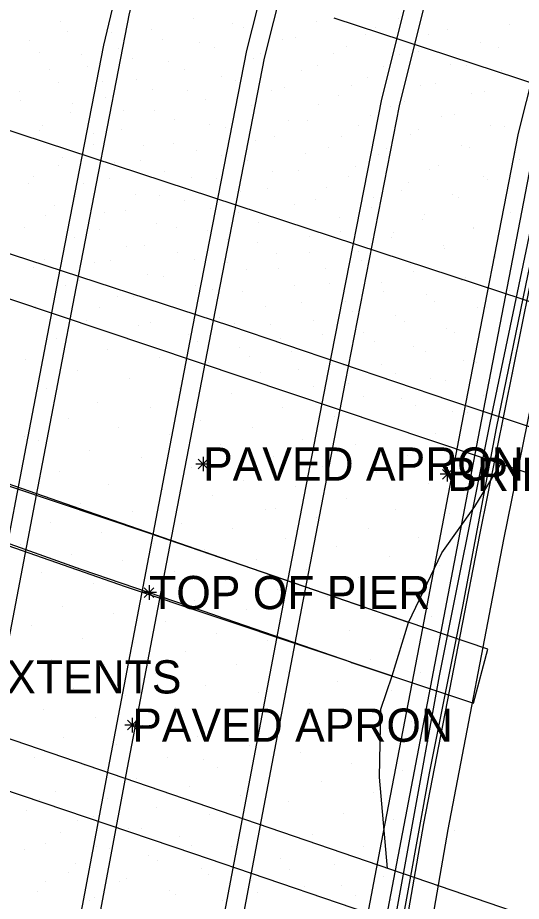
# Model space of a CAD drawing. Extents: x 1733582 to 1734070, y 467256 to 468256.
# Drawn here: x 1733841.15 to 1733868.45, y 467736.94 to 467784.83 of the extents above; entities that cross this region are included whole.
import ezdxf

# ---------------------------------------------------------------- set-up
doc = ezdxf.new("R2010")
doc.units = 0
for name, color, linetype in [('Default', 7, 'Continuous'), ('S_Bridge_Column_Square', 7, 'Continuous'), ('S_Bridge_Curb', 7, 'Continuous'), ('S_Bridge_Deck', 7, 'Continuous'), ('S_Bridge_Rail', 7, 'Continuous'), ('S_Ground_LevelString', 7, 'Continuous'), ('S_Ground_SpotElevation', 7, 'Continuous'), ('S_Guardrail_Beam', 7, 'Continuous'), ('S_Misc_MiscFeature', 7, 'Continuous'), ('S_Misc_MiscItems', 7, 'Continuous'), ('S_Roadway_Edge_Pavement', 7, 'Continuous'), ('S_Roadway_Painted_Lines', 7, 'Continuous'), ('S_Text', 7, 'Continuous')]:
    doc.layers.add(name, color=color, linetype=linetype)

# ---------------------------------------------------------------- blocks, each defined once
blk = doc.blocks.new('POINT_DISPLAY')
at = {"layer": 'Default'}
blk.add_line((0, 0), (0, 0), dxfattribs=at)

msp = doc.modelspace()

# ---------------------------------------------------------------- linework, layer by layer
at = {"layer": 'S_Bridge_Column_Square'}
msp.add_lwpolyline([(1733835.014, 467758.174), (1733846.976, 467754), (1733861.457, 467749.164), (1733862.347, 467752.05), (1733848.201, 467756.91), (1733835.866, 467761.044), (1733835.014, 467758.174)], dxfattribs=at)
at = {"layer": 'S_Bridge_Curb'}
msp.add_lwpolyline([(1733850.525, 467652.736), (1733851.676, 467663.636), (1733852.883, 467674.082), (1733854.262, 467685.548), (1733855.565, 467694.75), (1733856.845, 467703.748), (1733858.974, 467717.399), (1733861.233, 467731.524), (1733863.482, 467743.881), (1733865.283, 467752.922), (1733867.113, 467762.582), (1733868.83, 467770.933), (1733871.654, 467784.015), (1733874.05, 467794.414), (1733876.107, 467803.265), (1733877.952, 467810.863), (1733879.709, 467817.89), (1733881.379, 467824.23), (1733883.522, 467832.303), (1733885.6, 467839.734), (1733886.897, 467844.023)], dxfattribs=at)
at = {"layer": 'S_Bridge_Deck'}
msp.add_lwpolyline([(1733886.549, 467844.629), (1733884.683, 467838.178), (1733882.551, 467830.444), (1733878.067, 467813.135), (1733874.221, 467797.292), (1733871.125, 467783.729), (1733866.753, 467762.871), (1733863.994, 467749.165), (1733860.716, 467731.07), (1733858.373, 467716.77), (1733855.935, 467700.728), (1733853.766, 467684.771), (1733851.796, 467669.015), (1733850.46, 467656.5), (1733850.135, 467652.683), (1733850.236, 467652.213)], dxfattribs=at)
at = {"layer": 'S_Bridge_Rail'}
msp.add_lwpolyline([(1733886.303, 467841.899), (1733884.339, 467834.722), (1733880.236, 467819.247), (1733876.383, 467803.848), (1733872.741, 467788.157), (1733869.344, 467772.479), (1733866.194, 467756.807), (1733863.147, 467741.167), (1733860.402, 467725.353), (1733857.873, 467709.488), (1733855.573, 467693.7), (1733853.508, 467677.718), (1733851.616, 467661.907), (1733850.883, 467654.795)], dxfattribs=at)
at = {"layer": 'S_Ground_LevelString'}
for points in [[(1733862.347, 467752.05), (1733864.147, 467755.835), (1733865.928, 467758.336), (1733867.349, 467760.649)], [(1733861.204, 467738.727), (1733860.773, 467743.681), (1733860.839, 467747.366), (1733861.457, 467749.164)]]:
    msp.add_lwpolyline(points, dxfattribs=at)
at = {"layer": 'S_Guardrail_Beam'}
for points in [[(1733971.13, 467727.753), (1733959.189, 467731.849), (1733947.467, 467735.892), (1733935.587, 467740.11), (1733923.652, 467744.12), (1733911.999, 467748.09), (1733900.23, 467752.154), (1733888.348, 467756.158), (1733876.584, 467760.123), (1733864.636, 467764.075), (1733852.71, 467768.12), (1733840.864, 467771.985), (1733828.96, 467775.911), (1733821.157, 467778.362), (1733811.276, 467781.779), (1733806.138, 467783.487), (1733804.067, 467784.255), (1733803.797, 467784.235), (1733803.622, 467784.139), (1733803.485, 467783.985), (1733803.422, 467783.75), (1733803.437, 467783.569), (1733803.561, 467783.396)], [(1733779.584, 467763.162), (1733791.412, 467759.266), (1733803.188, 467755.466), (1733815.088, 467751.54), (1733826.834, 467747.566), (1733839.025, 467743.476), (1733850.692, 467739.538), (1733862.451, 467735.523), (1733874.35, 467731.517), (1733886.109, 467727.39), (1733889.984, 467726.018), (1733892.208, 467725.279), (1733893.28, 467725.008), (1733893.637, 467725.214), (1733893.817, 467725.531), (1733893.796, 467725.839), (1733893.658, 467726.063), (1733893.419, 467726.195)]]:
    msp.add_lwpolyline(points, dxfattribs=at)
at = {"layer": 'S_Misc_MiscFeature'}
for points in [[(1733826.53, 467660.119), (1733830.278, 467688.775), (1733833.202, 467711.396), (1733835.635, 467730.109), (1733838.854, 467747.125), (1733841.053, 467758.65), (1733843.35, 467770.62), (1733845.821, 467783.336), (1733847.212, 467789.204), (1733851.47, 467806.186), (1733857.516, 467830.268), (1733863.15, 467852.64)], [(1733864.079, 467852.275), (1733858.131, 467828.607), (1733852.049, 467804.339), (1733847.192, 467785.066), (1733844.207, 467769.696), (1733841.988, 467758.102), (1733839.394, 467744.549), (1733836.696, 467730.312), (1733833.835, 467708.583), (1733831.31, 467688.992), (1733827.509, 467659.844)], [(1733833.862, 467657.682), (1733837.178, 467683.156), (1733840.254, 467706.86), (1733843.003, 467727.895), (1733846.149, 467744.535), (1733848.346, 467756.071), (1733850.647, 467768.07), (1733853.573, 467783.047), (1733858.608, 467802.95), (1733864.671, 467827.038), (1733870.472, 467850.181)], [(1733871.393, 467849.822), (1733865.695, 467826.963), (1733859.504, 467802.42), (1733854.508, 467782.647), (1733851.621, 467767.768), (1733849.286, 467755.703), (1733847.085, 467744.185), (1733843.99, 467727.733), (1733841.143, 467705.862), (1733838.187, 467683.149), (1733834.828, 467657.424)], [(1733841.162, 467655.238), (1733844.601, 467681.503), (1733847.732, 467705.748), (1733850.338, 467725.565), (1733853.469, 467742.079), (1733855.705, 467753.836), (1733857.987, 467765.604), (1733860.885, 467780.409), (1733865.914, 467800.487), (1733872.136, 467825.216), (1733877.778, 467847.684)], [(1733878.753, 467847.484), (1733873.086, 467824.941), (1733866.9, 467800.334), (1733861.829, 467780.055), (1733858.912, 467765.093), (1733856.608, 467753.207), (1733854.359, 467741.368), (1733851.322, 467725.26), (1733848.676, 467705.17), (1733845.544, 467680.934), (1733842.168, 467654.979)], [(1733848.559, 467652.836), (1733852.024, 467679.791), (1733855.066, 467703.463), (1733857.598, 467722.922), (1733860.883, 467740.131), (1733863.02, 467751.281), (1733865.314, 467763.253), (1733868.31, 467778.566), (1733873.148, 467797.76), (1733879.142, 467821.53), (1733885.249, 467845.685)], [(1733849.555, 467652.651), (1733852.726, 467677.347), (1733855.925, 467702.233), (1733858.601, 467722.747), (1733863.855, 467750.228), (1733866.106, 467762.026), (1733869.19, 467777.948), (1733873.963, 467796.905), (1733880.016, 467820.978), (1733886.27, 467845.573)], [(1733887.367, 467840.604), (1733883.605, 467826.737), (1733879.636, 467811.346), (1733877.727, 467803.516), (1733874.188, 467788.265), (1733870.678, 467772.276), (1733867.49, 467756.558), (1733864.467, 467740.84), (1733861.741, 467725.141), (1733859.155, 467709.272), (1733856.917, 467693.32), (1733854.838, 467677.445), (1733853.015, 467661.799), (1733852.333, 467655.629)], [(1733866.647, 467750.615), (1733860.076, 467752.833), (1733860.036, 467752.849), (1733852.751, 467755.357), (1733852.653, 467755.397), (1733845.408, 467757.906), (1733845.361, 467757.924), (1733838.187, 467760.422), (1733838.141, 467760.443), (1733831.583, 467762.612), (1733830.756, 467759.752), (1733837.3, 467757.526), (1733837.424, 467757.497), (1733844.577, 467754.95), (1733844.636, 467754.93), (1733851.762, 467752.482), (1733851.91, 467752.431), (1733859.188, 467749.921), (1733859.254, 467749.894), (1733865.861, 467747.686), (1733866.647, 467750.615)], [(1733862.347, 467752.05), (1733864.147, 467755.835), (1733865.928, 467758.336), (1733867.349, 467760.649)], [(1733861.204, 467738.727), (1733860.773, 467743.681), (1733860.839, 467747.366), (1733861.457, 467749.164)]]:
    msp.add_lwpolyline(points, dxfattribs=at)
at = {"layer": 'S_Misc_MiscItems'}
for p, q in [((1733851.597, 467760.642), (1733850.811, 467760.642)), ((1733851.466, 467760.38), (1733850.942, 467760.904)), ((1733851.466, 467760.904), (1733850.942, 467760.38)), ((1733851.204, 467761.035), (1733851.204, 467760.249)), ((1733864.832, 467760.087), (1733864.046, 467760.087)), ((1733864.701, 467759.825), (1733864.177, 467760.349)), ((1733864.701, 467760.349), (1733864.177, 467759.825)), ((1733864.439, 467760.48), (1733864.439, 467759.694)), ((1733848.541, 467753.416), (1733848.017, 467753.94)), ((1733848.541, 467753.94), (1733848.017, 467753.416)), ((1733848.279, 467754.071), (1733848.279, 467753.285)), ((1733848.672, 467753.678), (1733847.886, 467753.678)), ((1733847.624, 467746.229), (1733847.1, 467746.753)), ((1733847.624, 467746.753), (1733847.1, 467746.229)), ((1733847.362, 467746.884), (1733847.362, 467746.098)), ((1733847.755, 467746.491), (1733846.969, 467746.491))]:
    msp.add_line(p, q, dxfattribs=at)
at = {"layer": 'S_Roadway_Edge_Pavement'}
for points in [[(1733611.876, 467844.635), (1733674.83, 467825.942), (1733744.192, 467804.366), (1733759.494, 467799.192), (1733788.268, 467787.576), (1733794.963, 467784.321), (1733814.735, 467777.995), (1733835.64, 467771.291), (1733878.809, 467756.802), (1733915.97, 467744.059), (1733950.334, 467732.351), (1733979.802, 467721.488), (1733993.679, 467716.295), (1734030.704, 467703.141), (1734054.753, 467695.101)], [(1734047.514, 467668.647), (1734012.708, 467681.197), (1733935.599, 467708.176), (1733908.807, 467722.422), (1733806.077, 467757.609), (1733715.329, 467786.896), (1733665.166, 467802.478), (1733604.388, 467822.173)]]:
    msp.add_lwpolyline(points, dxfattribs=at)
at = {"layer": 'S_Roadway_Painted_Lines'}
msp.add_line((1733858.283, 467784.833), (1733872.566, 467780.13), dxfattribs=at)
msp.add_lwpolyline([(1733613.543, 467849.189), (1733648.882, 467838.819), (1733697.382, 467824.233), (1733741.485, 467810.479), (1733805.714, 467790.022), (1733833.501, 467781.081), (1733877.654, 467766.584), (1733913.643, 467754.586), (1734001.896, 467724.119), (1734057.373, 467704.28)], dxfattribs=at)

# ---------------------------------------------------------------- block references
at = {"layer": 'S_Ground_SpotElevation'}
for p in [(1733843.451, 467784.652), (1733850.692, 467784.812), (1733852.789, 467784.513), (1733857.371, 467784.647), (1733861.798, 467784.815), (1733843.827, 467784.071), (1733846.25, 467784.036), (1733848.389, 467784.198), (1733853.384, 467784.286), (1733860.574, 467784.31), (1733864.443, 467784.17), (1733867.829, 467784.449), (1733841.818, 467783.587), (1733849.004, 467783.654), (1733855.528, 467783.65), (1733856.236, 467783.747), (1733860.008, 467783.903), (1733863.42, 467783.897), (1733846.637, 467783.17), (1733851.032, 467783.469), (1733851.842, 467783.191), (1733858.991, 467783.275), (1733866.229, 467783.515), (1733867.238, 467783.23), (1733842.31, 467782.943), (1733844.585, 467782.852), (1733847.383, 467782.626), (1733853.923, 467782.634), (1733854.301, 467782.882), (1733858.277, 467782.894), (1733861.837, 467782.818), (1733862.861, 467783.015), (1733844.927, 467782.181), (1733849.323, 467782.481), (1733857.379, 467782.222), (1733860.959, 467782.164), (1733864.594, 467782.318), (1733865.491, 467782.237), (1733842.883, 467782.048), (1733850.173, 467782.03), (1733852.209, 467781.645), (1733856.512, 467781.982), (1733867.355, 467781.945), (1733843.35, 467781.318), (1733845.763, 467781.391), (1733847.582, 467781.46), (1733852.968, 467781.423), (1733859.241, 467781.165), (1733860.122, 467781.573), (1733862.963, 467781.165), (1733863.806, 467781.272), (1733868.191, 467781.532), (1733841.268, 467780.841), (1733848.46, 467780.932), (1733850.381, 467780.877), (1733854.905, 467780.865), (1733855.617, 467781.029), (1733865.745, 467780.702), (1733866.465, 467780.816), (1733841.323, 467780.366), (1733845.889, 467780.485), (1733851.344, 467780.407), (1733858.53, 467780.604), (1733862.111, 467780.302), (1733844.114, 467780.187), (1733846.866, 467779.821), (1733848.555, 467779.78), (1733852.978, 467780.086), (1733853.802, 467780.097), (1733857.465, 467780.123), (1733861.344, 467780.031), (1733844.035, 467779.692), (1733849.654, 467779.293), (1733855.857, 467779.245), (1733856.876, 467779.258), (1733860.286, 467779.541), (1733864.128, 467779.5), (1733864.822, 467779.596), (1733842.49, 467779.002), (1733846.805, 467778.764), (1733851.531, 467779.024), (1733852.431, 467778.864), (1733859.645, 467778.968), (1733866.805, 467778.987), (1733867.535, 467778.921), (1733842.354, 467778.735), (1733845.283, 467778.553), (1733855.097, 467778.375), (1733858.692, 467778.368), (1733862.437, 467778.477), (1733862.906, 467778.748), (1733845.263, 467777.948), (1733847.984, 467777.889), (1733849.619, 467778.012), (1733854.037, 467778.163), (1733858.024, 467777.817), (1733865.213, 467777.92), (1733850.824, 467777.655), (1733852.204, 467777.386), (1733856.743, 467777.47), (1733860.722, 467777.393), (1733861.141, 467777.726), (1733865.672, 467777.797), (1733868.018, 467777.518), (1733843.579, 467777.27), (1733846.426, 467776.969), (1733847.807, 467777.106), (1733853.631, 467777.078), (1733868.354, 467777.132), (1733843.363, 467776.818), (1733849.099, 467776.496), (1733854.963, 467776.482), (1733856.4, 467776.538), (1733859.472, 467776.789), (1733863.471, 467776.592), (1733863.969, 467776.826), (1733841.984, 467776.24), (1733846.115, 467776.135), (1733850.587, 467776.172), (1733851.914, 467776.112), (1733859.082, 467776.247), (1733862.336, 467775.924), (1733866.411, 467776.225), (1733866.619, 467776.075), (1733841.734, 467775.86), (1733844.74, 467775.838), (1733853.244, 467775.435), (1733854.674, 467775.596), (1733857.919, 467775.635), (1733861.941, 467775.49), (1733844.282, 467775.12), (1733847.554, 467775.248), (1733848.856, 467775.178), (1733850.195, 467774.945), (1733857.301, 467774.974), (1733860.434, 467775.085), (1733864.724, 467775.253), (1733865.03, 467775.104), (1733843.148, 467774.634), (1733851.588, 467774.518), (1733856.134, 467774.701), (1733860.32, 467774.527), (1733867.509, 467774.476), (1733842.64, 467774.126), (1733845.875, 467774.26), (1733847.021, 467774.407), (1733853.122, 467774.287), (1733858.617, 467774.012), (1733863.217, 467774.15), (1733867.841, 467774.299), (1733848.674, 467773.676), (1733854.212, 467773.755), (1733855.756, 467773.748), (1733863.12, 467773.915), (1733841.506, 467773.459), (1733845.562, 467773.329), (1733849.782, 467773.451), (1733851.416, 467773.289), (1733858.677, 467773.23), (1733861.506, 467773.171), (1733865.875, 467773.397), (1733865.888, 467773.463), (1733844.239, 467772.918), (1733852.507, 467772.789), (1733854.141, 467772.631), (1733856.995, 467772.976), (1733861.43, 467772.91), (1733843.681, 467772.386), (1733847.059, 467772.445), (1733848.047, 467772.501), (1733849.834, 467772.087), (1733855.18, 467772.053), (1733856.989, 467772.1), (1733859.636, 467772.181), (1733864.223, 467772.489), (1733864.282, 467772.315), (1733842.604, 467771.741), (1733846.205, 467771.658), (1733850.716, 467771.753), (1733859.764, 467771.7), (1733867.033, 467771.885), (1733867.053, 467771.856), (1733841.985, 467771.287), (1733845.342, 467771.552), (1733852.539, 467771.561), (1733853.578, 467771.166), (1733855.304, 467771.235), (1733857.861, 467771.247), (1733862.432, 467771.45), (1733862.629, 467771.102), (1733848.167, 467770.938), (1733849.069, 467770.806), (1733865.412, 467770.747), (1733843.764, 467770.323), (1733844.491, 467770.576), (1733850.765, 467770.338), (1733856.133, 467770.341), (1733858.07, 467770.402), (1733860.898, 467770.492), (1733865.185, 467770.568), (1733846.581, 467769.727), (1733847.419, 467769.742), (1733851.691, 467770.111), (1733853.333, 467769.968), (1733860.992, 467769.999), (1733863.297, 467769.823), (1733867.803, 467770.073), (1733849.269, 467769.233), (1733854.566, 467769.178), (1733856.515, 467769.393), (1733858.95, 467769.443), (1733863.754, 467769.438), (1733842.121, 467769.164), (1733845.591, 467769.104), (1733850.048, 467768.963), (1733859.307, 467768.903), (1733866.058, 467769.149), (1733866.553, 467769.123), (1733844.876, 467768.44), (1733848.363, 467768.317), (1733852.114, 467768.604), (1733852.931, 467768.251), (1733857.214, 467768.446), (1733861.648, 467768.667), (1733862.105, 467768.394), (1733847.715, 467768.15), (1733854.84, 467768.188), (1733859.924, 467767.761), (1733864.401, 467767.978), (1733864.821, 467767.78), (1733843.234, 467767.444), (1733850.417, 467767.661), (1733850.888, 467767.304), (1733855.413, 467767.458), (1733857.695, 467767.682), (1733860.492, 467767.272), (1733867.14, 467767.272), (1733846.021, 467766.871), (1733853.203, 467766.938), (1733858.222, 467766.825), (1733862.625, 467767.018), (1733848.844, 467766.416), (1733853.698, 467766.49), (1733856.017, 467766.73), (1733863.278, 467766.739), (1733841.581, 467766.287), (1733851.48, 467766.169), (1733858.835, 467765.98), (1733860.853, 467766.038), (1733865.313, 467766.276), (1733866.027, 467766.169), (1733844.381, 467765.7), (1733854.297, 467765.611), (1733856.397, 467765.758), (1733861.62, 467765.539), (1733868.045, 467765.542), (1733847.194, 467765.264), (1733859.08, 467765.027), (1733863.508, 467765.266), (1733864.361, 467765.166), (1733842.705, 467764.738), (1733849.919, 467764.737), (1733852.73, 467764.453), (1733857.179, 467764.82), (1733845.495, 467763.999), (1733859.891, 467764.277), (1733861.978, 467764.174), (1733866.377, 467764.364), (1733848.34, 467763.697), (1733855.489, 467763.689), (1733862.709, 467763.839), (1733864.744, 467763.48), (1733843.902, 467763.13), (1733851.055, 467763.025), (1733858.342, 467763.228), (1733865.552, 467763.429), (1733846.622, 467762.613), (1733853.883, 467762.628), (1733861.123, 467762.768), (1733867.47, 467762.721), (1733841.511, 467762.128), (1733849.391, 467762.218), (1733856.614, 467761.993), (1733863.819, 467762.307), (1733842.265, 467761.945), (1733852.155, 467761.69), (1733859.455, 467761.704), (1733845.058, 467761.397), (1733855.02, 467761.065), (1733862.258, 467761.102), (1733847.859, 467760.972), (1733843.404, 467760.221), (1733850.573, 467760.47), (1733857.654, 467760.502), (1733860.582, 467760.168), (1733864.854, 467760.437), (1733853.42, 467759.774), (1733841.756, 467759.228), (1733846.093, 467759.554), (1733848.997, 467759.238), (1733856.225, 467759.42), (1733863.44, 467759.582), (1733851.695, 467758.914), (1733858.978, 467758.782), (1733844.566, 467758.497), (1733854.568, 467758.174), (1733855.113, 467758.256), (1733861.649, 467758.164), (1733847.364, 467758.07), (1733857.366, 467757.758), (1733864.569, 467757.963), (1733842.947, 467757.467), (1733850.045, 467757.436), (1733845.69, 467756.946), (1733852.818, 467757.13), (1733860.144, 467757.158), (1733841.315, 467756.29), (1733848.492, 467756.363), (1733855.675, 467756.611), (1733862.905, 467756.677), (1733851.294, 467755.996), (1733858.446, 467756.165), (1733844.093, 467755.749), (1733846.839, 467755.389), (1733854.09, 467755.446), (1733861.295, 467755.652), (1733849.629, 467754.813), (1733856.799, 467754.933), (1733864.035, 467755.135), (1733842.429, 467754.77), (1733852.408, 467754.332), (1733859.62, 467754.515), (1733845.241, 467754.192), (1733862.37, 467753.88), (1733847.989, 467753.677), (1733855.216, 467753.847), (1733857.954, 467753.475), (1733843.555, 467752.897), (1733850.762, 467753.245), (1733846.324, 467752.527), (1733853.571, 467752.766), (1733860.754, 467752.795), (1733849.148, 467752.125), (1733856.369, 467752.095), (1733863.565, 467752.359), (1733841.926, 467751.874), (1733859.146, 467751.624), (1733844.664, 467751.189), (1733851.941, 467751.437), (1733854.67, 467751.088), (1733861.931, 467751.185), (1733847.509, 467750.974), (1733857.458, 467750.516), (1733842.992, 467750.075), (1733850.269, 467750.466), (1733860.291, 467750.041), (1733845.86, 467749.788), (1733853.038, 467749.778), (1733848.613, 467749.306), (1733855.794, 467749.386), (1733862.977, 467749.331), (1733841.368, 467749.061), (1733851.356, 467748.653), (1733858.514, 467748.881), (1733844.178, 467748.503), (1733846.983, 467748.118), (1733854.232, 467748.287), (1733861.404, 467748.356), (1733856.963, 467747.652), (1733842.547, 467747.324), (1733849.705, 467747.466), (1733852.424, 467747.272), (1733845.387, 467746.933), (1733859.738, 467747.079), (1733862.495, 467746.687), (1733847.916, 467746.49), (1733855.389, 467746.638), (1733843.657, 467745.807), (1733850.916, 467745.877), (1733858.146, 467746.109), (1733846.496, 467745.453), (1733853.74, 467745.382), (1733860.935, 467745.699), (1733856.461, 467745.007), (1733842.086, 467744.747), (1733844.798, 467744.281), (1733849.276, 467744.735), (1733851.241, 467744.654), (1733859.258, 467744.428), (1733851.962, 467744.222), (1733862.027, 467744.007), (1733847.61, 467743.619), (1733854.826, 467743.657), (1733857.645, 467743.45), (1733843.204, 467742.895), (1733850.461, 467743.148), (1733842.331, 467742.487), (1733846.039, 467742.522), (1733846.801, 467742.47), (1733853.228, 467742.705), (1733855.831, 467742.371), (1733860.446, 467742.836), (1733848.66, 467742.023), (1733841.607, 467741.864), (1733845.285, 467741.542), (1733851.546, 467741.632), (1733858.812, 467741.702), (1733844.4, 467741.335), (1733854.324, 467741.218), (1733861.537, 467741.363), (1733843.448, 467740.699), (1733847.142, 467740.874), (1733847.84, 467740.881), (1733857.136, 467740.582), (1733864.843, 467740.782), (1733842.639, 467740.101), (1733849.951, 467740.432), (1733850.576, 467739.978), (1733841.523, 467739.775), (1733845.437, 467739.929), (1733846.15, 467739.831), (1733852.748, 467739.916), (1733859.923, 467739.922), (1733848.258, 467739.406), (1733848.705, 467739.167), (1733855.42, 467739.245), (1733844.303, 467738.989), (1733851.104, 467738.701), (1733855.91, 467738.659), (1733858.32, 467738.936), (1733843.884, 467738.502), (1733847.028, 467738.167), (1733851.51, 467738.378), (1733853.831, 467738.093), (1733860.997, 467738.294), (1733842.634, 467738.017), (1733846.663, 467738.035), (1733856.685, 467737.741), (1733858.696, 467737.802), (1733842.232, 467737.498), (1733845.338, 467737.176), (1733849.375, 467737.504), (1733849.734, 467737.301), (1733854.178, 467737.441), (1733859.467, 467737.259), (1733845.023, 467737.005), (1733852.239, 467737), (1733861.424, 467737.05)]:
    msp.add_blockref('POINT_DISPLAY', p, dxfattribs=at)

# ---------------------------------------------------------------- texts
at = {"layer": 'S_Text'}
for s, p in [('PAVED APRON', (1733851.204, 467759.742)), ('BRIDGE DRAIN', (1733864.439, 467759.187)), ('TOP OF PIER', (1733848.279, 467752.778)), ('BRIDGE EXTENTS', (1733829.033, 467748.209)), ('PAVED APRON', (1733847.362, 467745.591))]:
    msp.add_text(s, height=1.8, dxfattribs=at).set_placement(p)

doc.saveas('drawing.dxf')
